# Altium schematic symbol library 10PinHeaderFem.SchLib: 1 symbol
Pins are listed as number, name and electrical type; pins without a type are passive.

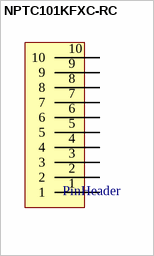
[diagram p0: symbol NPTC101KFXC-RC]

## NPTC101KFXC-RC
designator PinHeader
Sullins Connector Solutions 10 pin female header. SMD.
footprint NPTC101KFXC-RC (Sullins Connector Solutions 10 pin female header. SMD.)
pins: 1, 2, 3, 4, 5, 6, 7, 8, 9, 10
